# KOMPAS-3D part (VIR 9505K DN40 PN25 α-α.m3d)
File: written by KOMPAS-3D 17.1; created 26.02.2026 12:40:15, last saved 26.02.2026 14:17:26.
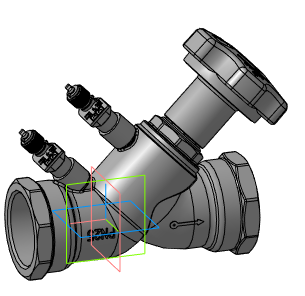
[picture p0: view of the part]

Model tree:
1. Операция без истории:4  (labels: VIR 9505K DN40 PN25 р-р)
